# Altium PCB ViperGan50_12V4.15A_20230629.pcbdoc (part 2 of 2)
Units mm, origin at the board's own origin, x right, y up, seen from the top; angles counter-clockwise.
Board outline 450.19 x 402.29 mm, 2 copper layers (Top Layer, Bottom Layer); 71 components, 42 nets, 203 pads, 97 vias.
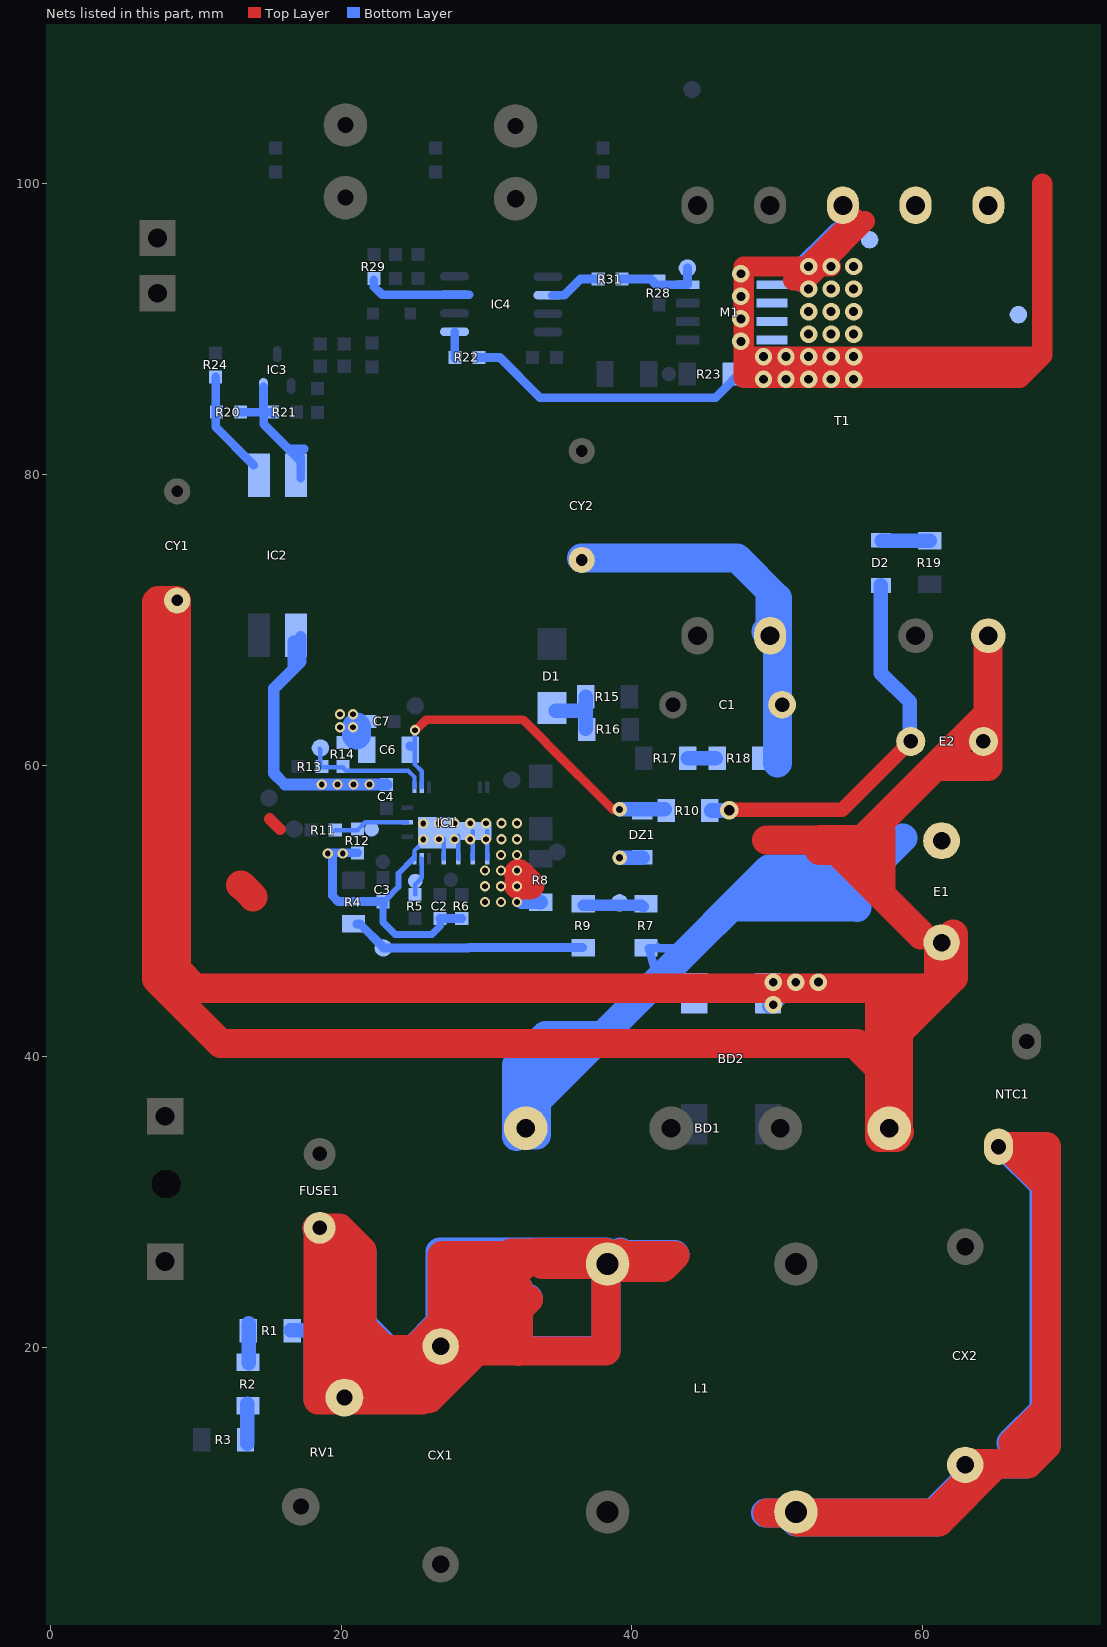
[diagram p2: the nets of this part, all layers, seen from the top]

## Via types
v1: diameter 1.2, hole 0.6, Top Layer to Bottom Layer, 55 vias
v2: diameter 0.7, hole 0.4, Top Layer to Bottom Layer, 38 vias
v3: diameter 1, hole 0.5, Top Layer to Bottom Layer, 3 vias
v4: diameter 1.27, hole 0.711, Top Layer to Bottom Layer, 1 vias

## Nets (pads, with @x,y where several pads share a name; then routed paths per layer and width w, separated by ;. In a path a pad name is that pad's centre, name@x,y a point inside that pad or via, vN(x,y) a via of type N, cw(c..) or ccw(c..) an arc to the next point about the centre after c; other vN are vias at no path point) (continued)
NetCX1_2: CX1.2 FUSE1.1 L1.4 R1.1 RV1.1 | length 356.6
  Top Layer w1: 18.706,21.106 19.296,21.106
  Top Layer w2: FUSE1.1@18.35,28.2 FUSE1.1@18.525,28.2 19.875,28.2 21.425,26.65 21.425,21.775 ; 18.4,20.575 FUSE1.1@18.4,28.075 ; 18.4,20.8 18.4,16.375 25.6,16.375 25.7,16.475 ; 19.175,18.2 20.225,18.2 ; RV1.1@19.7,17.025 RV1.1@20.225,17.025 ; 19.725,22.85 19.725,27.275 ; 20.225,22.625 20.225,18.2 ; 20.225,22.975 21.425,21.775 ; 21.175,19.825 21.425,19.825 ; 21.2,21.6 23.15,19.65 ; 21.425,18.275 21.425,19.825 ; 21.425,21.35 21.425,21.775 ; 25.6,19.825 25.025,19.825 ; 25.675,17.55 25.925,17.8 ; CX1.2@26.95,20.575 26.95,21.75 ; 28.15,22.6 28.15,22.95 ; 32.2,19.7 32.2,19.725 ; 32.2,23.975 32.2,22.6 ; 32.875,23.275 32.2,22.6 ; L1.4@38.475,25.475 42.15,25.475 42.975,26.3 L1.4@39.025,26.3 ; L1.4@39.2,26.475 L1.4@39.025,26.3 ; RV1.1@20.225,17.025 22.225,17.025 ; RV1.1@20.225,17.025 RV1.1@20.225,16.525 20.225,16.475 21.675,16.475 ; RV1.1@20.225,17.025 20.225,18.2 ; 20.225,18.2 23.4,18.2 ; 21.425,19.825 23.375,19.825 25.025,19.825 ; 21.425,19.825 21.425,20.6 ; 21.425,20.6 20.85,20.025 20.3,20.025 21.425,21.15 21.425,20.6 ; 21.675,16.475 22.225,17.025 ; 21.675,16.475 25.375,16.475 ; 22.225,17.025 23.4,18.2 ; 22.225,17.025 25.925,17.025 ; 23.4,18.2 25.025,19.825 ; 23.4,18.2 25.925,18.2 ; 25.025,19.825 26.95,21.75 ; 25.375,16.475 25.925,17.025 ; 25.375,16.475 25.7,16.475 ; 25.7,16.475 26.075,16.475 29.325,19.725 ; 25.925,17.025 25.925,17.8 ; 25.925,17.8 27.85,19.725 29.325,19.725 ; 25.925,17.8 25.925,18.2 ; 25.925,18.2 25.925,19.85 26.15,20.075 26.975,20.075 33.2,26.3 ; 26.95,21.75 28.15,22.95 ; 26.95,21.75 26.95,26.3 28.15,26.3 ; 28.15,22.95 31.5,26.3 ; 28.15,22.95 28.15,26.3 ; 28.15,26.3 31.5,26.3 ; 29.325,19.725 32.2,19.725 ; 29.325,19.725 32.2,22.6 ; 31.5,26.3 33.2,26.3 ; 31.5,26.3 31.675,26.475 33.375,26.475 ; 32.2,19.725 38.225,19.725 L1.4@38.225,25.675 ; 32.2,19.725 32.2,22.6 ; 33.2,26.3 L1.4@38.225,26.3 ; 33.2,26.3 33.825,25.675 L1.4@38.225,25.675 ; 33.2,26.3 33.375,26.475 ; 33.375,26.475 33.4,26.5 38.225,26.5 L1.4@38.225,26.3 ; L1.4@38.225,25.675 38.4,25.675 L1.4@39.025,26.3 ; L1.4@38.225,25.675 L1.4@38.225,26.3 ; L1.4@38.225,26.3 L1.4@39.025,26.3
  Bottom Layer w1: R1.1@16.553,21.156 18.475,21.156 19.296,21.156
  Bottom Layer w2: FUSE1.1@18.35,28.15 FUSE1.1@18.475,28.15 ; 18.4,20.85 18.4,16.425 25.6,16.425 25.7,16.525 ; 18.475,20.625 18.475,21.156 FUSE1.1@18.475,28.15 ; FUSE1.1@18.475,28.2 FUSE1.1@18.475,28.15 ; 19.175,18.25 20.225,18.25 ; RV1.1@19.7,17.075 RV1.1@20.225,17.075 ; 20.225,27.375 20.225,18.25 ; 20.3,20.075 20.85,20.075 ; 21.3,21.7 23.125,19.875 ; 21.325,19.825 21.425,19.825 ; 21.425,18.325 21.425,19.825 ; 25.675,17.6 25.925,17.85 ; CX1.2@25.75,19.825 24.975,19.825 ; CX1.2@27.275,19.75 CX1.2@26.9,20.125 ; 28.375,21.3 28.375,21.525 ; 32.2,19.75 32.2,19.775 ; 32.2,24.025 32.2,22.65 ; 32.875,23.325 32.2,22.65 ; L1.4@38.475,25.525 42.15,25.525 42.975,26.35 L1.4@39.025,26.35 ; L1.4@39.2,26.525 L1.4@39.025,26.35 ; FUSE1.1@18.475,28.15 19.8,28.15 21.425,26.525 21.425,19.825 ; RV1.1@20.225,17.075 22.225,17.075 ; RV1.1@20.225,17.075 RV1.1@20.225,16.525 21.675,16.525 ; RV1.1@20.225,17.075 20.225,18.25 ; 20.225,18.25 23.4,18.25 ; 21.425,19.825 24.975,19.825 ; 21.675,16.525 25.375,16.525 ; 21.675,16.525 22.225,17.075 ; 22.225,17.075 25.925,17.075 ; 22.225,17.075 23.4,18.25 ; 23.4,18.25 24.975,19.825 ; 23.4,18.25 25.925,18.25 ; 24.975,19.825 26.8,21.65 ; 25.375,16.525 25.7,16.525 ; 25.375,16.525 25.925,17.075 ; 25.7,16.525 26.075,16.525 29.325,19.775 ; 25.925,17.075 25.925,17.85 ; 25.925,17.85 27.85,19.775 29.325,19.775 ; 25.925,17.85 25.925,18.25 ; 25.925,18.25 25.925,19.9 26.15,20.125 CX1.2@26.9,20.125 ; 26.8,21.65 28.375,23.225 ; 26.8,21.65 26.8,26.525 28.375,26.525 ; 26.8,21.65 26.8,20.225 CX1.2@26.9,20.125 ; CX1.2@26.9,20.125 26.975,20.125 28.375,21.525 ; 28.375,21.525 33.2,26.35 ; 28.375,21.525 28.375,23.225 ; 28.375,23.225 28.375,26.525 ; 28.375,23.225 31.675,26.525 ; 28.375,26.525 31.675,26.525 ; 29.325,19.775 32.2,22.65 ; 29.325,19.775 32.2,19.775 ; 31.675,26.525 33.375,26.525 ; 32.2,19.775 32.2,22.65 ; 32.2,19.775 38.225,19.775 L1.4@38.225,25.725 ; 33.2,26.35 33.375,26.525 ; 33.2,26.35 33.825,25.725 L1.4@38.225,25.725 ; 33.2,26.35 L1.4@38.225,26.35 ; 33.375,26.525 33.4,26.55 38.225,26.55 L1.4@38.225,26.35 ; L1.4@38.225,25.725 38.4,25.725 L1.4@39.025,26.35 ; L1.4@38.225,25.725 L1.4@38.225,26.35 ; L1.4@38.225,26.35 L1.4@39.025,26.35
NetCX2_1: CX2.1 L1.2 NTC1.2 | length 136.1
  Top Layer w2: 49.325,8.575 L1.2@51.428,8.575 ; L1.2@51.428,8.66 L1.2@51.428,8.575 ; 65.025,11.9 61.1,7.975 51.428,7.975 L1.2@51.428,8.575 ; NTC1.2@65.354,33.778 NTC1.2@65.847,33.778 ; 66.222,13.4 68.497,15.675 ; 68.325,31.3 NTC1.2@65.847,33.778 ; L1.2@51.428,8.575 60.85,8.575 63.075,10.8 63.075,11.9 63.15,11.975 67.25,11.975 68.497,13.222 68.497,15.675 ; NTC1.2@65.847,33.778 68.497,33.778 68.497,15.675
  Bottom Layer w2: 49.175,8.575 L1.2@51.278,8.575 ; L1.2@51.278,8.66 L1.2@51.278,8.575 ; 64.875,11.9 60.95,7.975 51.278,7.975 L1.2@51.278,8.575 ; NTC1.2@65.204,33.778 NTC1.2@65.697,33.778 ; 66.072,13.4 68.347,15.675 ; 68.175,31.3 NTC1.2@65.697,33.778 ; L1.2@51.278,8.575 60.7,8.575 62.925,10.8 CX2.1@62.925,11.9 63,11.975 67.1,11.975 68.347,13.222 68.347,15.675 ; NTC1.2@65.697,33.778 68.347,33.778 68.347,15.675
NetD1_K: D1.K R15.1 R16.1 | length 4.2
  Bottom Layer w1: D1.K@34.775,63.775 36.825,63.775 ; R16.1@36.825,62.525 36.825,63.775 ; R15.1@36.825,64.725 36.825,63.775
NetD2_A: D2.A R19.1 | length 3.3
  Bottom Layer w1: D2.A@57.175,75.45 R19.1@60.475,75.45
NetD2_K: D2.K E2.1 R10.1 | length 26.8
  Top Layer w1: v4@47,56.95 54.475,56.95 E2.1@59.175,61.65
  Bottom Layer w1: R10.1@45.45,56.9 v4@46.45,56.9 ; D2.K@57.125,72.375 57.125,66.35 59.1,64.375 E2.1@59.1,61.5
  other v4: 46.7,56.925
NetIC1_6: IC1.6 pad.11@25.1,52.05 R5.2 | length 2.7
  Bottom Layer w0.3: R5.2@25.095,51.126 25.095,51.82 25.548,52.273 IC1.6@25.548,53.594
NetIC1_9: IC1.9 pad.11@22.1,55.6 R11.2 R12.2 | length 5.2
  Bottom Layer w0.3: R11.2@19.596,55.55 21.121,55.55 21.133,55.562 21.665,56.094 IC1.9@24.548,56.094
NetIC1_11: IC1.11 pad.11@18.575,61.2 R13.1 R14.1 | length 8.6
  Bottom Layer w0.3: pad.11@18.525,61.15 18.575,61.1 18.575,60.025 R13.1@18.681,59.919 ; R13.1@18.745,59.868 20.117,59.868 20.36,59.625 24.625,59.625 25.048,59.202 IC1.11@25.048,58.494
NetIC2_1: IC2.1 R20.1 R24.2 | length 7.2
  Bottom Layer w0.6: R24.2@11.375,86.725 11.375,83.275 IC2.1@14,80.65
NetIC4_2: IC4.2 R31.2 | length 3.6
  Bottom Layer w0.6: IC4.2@34.531,92.341 35.344,92.341 36.449,93.447 R31.2@37.681,93.447
NetIC4_5: IC4.5 R22.2 | length 1.8
  Bottom Layer w0.6: R22.2@27.814,88.011 IC4.5@27.814,89.827
NetIC4_7: IC4.7 R29.2 | length 7.2
  Bottom Layer w0.6: R29.2@22.25,93.409 22.25,92.939 22.822,92.367 IC4.7@27.8,92.367 IC4.7@28.791,92.367
NetM1_D: M1.D pad.26@56.35,96.15 pad.26@66.575,91 R22.1 R23.1 T1.2 T1.3 | length 123.7
  Top Layer w1.4: 47.811,87.7 52.146,87.7 55.245,87.7 67.475,87.7 ; 51.075,93.375 v1@52.014,94.314 ; v1@51.775,93.175 52.914,94.314 ; v1(53.696,94.314) 52.914,94.314 ; T1.3@55.325,97.625 v1@52.014,94.314 ; 56.025,97.425 52.914,94.314 ; 67.575,88.1 47.686,88.1 ; 68.225,100 68.225,88.2 66.686,86.661 47.686,86.661 47.686,88.1 ; 47.686,88.1 47.686,94.314 v1@52.014,94.314 ; v1@52.014,94.314 v1(52.146,94.314) 52.914,94.314
  Bottom Layer w0.6: R22.1@29.476,88.062 30.913,88.062 33.682,85.293 45.745,85.293 47.969,87.517 48.971,87.517
  Bottom Layer w2: 51.525,93.625 54.3,96.4
  other v1: 49.047,86.567 50.597,86.567 52.146,86.567 53.696,86.567 55.245,86.567 49.047,88.117 50.597,88.117 52.146,88.117 53.696,88.117 55.245,88.117 47.498,89.158 52.146,89.666 53.696,89.666 55.245,89.666 47.498,90.708 52.146,91.216 53.696,91.216 55.245,91.216 47.498,92.257 52.146,92.765 53.696,92.765 55.245,92.765 47.498,93.806 55.245,94.314
NetM1_G: M1.G pad.26@43.815,94.209 R28.2 R31.1 | length 5.8
  Bottom Layer w0.6: R31.1@39.319,93.447 41.3,93.447 41.681,93.066 M1.G@43.825,93.066 ; pad.26@43.815,94.209 43.825,94.199 M1.G@43.825,93.066 ; M1.G@43.834,93.066 M1.G@43.825,93.066
NetR1_2: R1.2 R2.1 | length 2.7
  Bottom Layer w1: R2.1@13.644,18.903 R1.2@13.644,21.646
NetR2_2: R2.2 R3.1 | length 2.7
  Bottom Layer w1: R3.1@13.544,13.353 R2.2@13.544,16.096
NetR4_2: pad.11@22.9,47.45 R4.2 R9.1 | length 16.2
  Bottom Layer w0.6: R4.2@21.1,49.1 21.3,49.1 pad.11@22.9,47.5 ; pad.11@22.9,47.45 28.775,47.45 28.8,47.475 R9.1@36.625,47.475
NetR7_1: pad.11@39.15,50.55 R7.1 R9.2 | length 4.2
  Bottom Layer w0.8: R9.2@36.65,50.395 40.655,50.395 R7.1@40.775,50.275
NetR17_2: R17.2 R18.1 | length 1.9
  Bottom Layer w1: R17.2@43.825,60.5 R18.1@45.75,60.5
OUT: IC2.2 IC3.3 R20.2 R21.2 | length 10.9
  Bottom Layer w0.6: R20.2@13.143,84.293 14.669,84.293 ; IC3.3@14.669,86.022 14.669,84.293 ; 14.675,84.35 14.675,84.293 ; R21.2@15.291,84.303 15.301,84.293 14.675,84.293 ; R21.2@15.329,84.226 15.329,84.163 R21.2@15.342,84.15 ; 16.462,81.763 17.463,81.763 ; IC2.2@17.225,79.775 IC2.2@17.225,80.925 ; IC2.2@17.225,81.225 IC2.2@17.225,80.925 ; 14.669,84.293 14.675,84.293 ; 14.675,84.293 14.675,83.475 IC2.2@17.225,80.925
PGND: BD1.4 BD2.4 C2.2 C3.1 C4.2 C6.2 C7.2 CY1.2 DZ1.A E1.2 E2.2 IC1.1 IC1.2 IC1.3 IC1.4 IC1.7 IC1.17 IC2.3 R6.1 R8.2 R12.1 R14.2 T1.10 | length 312.5
  Top Layer w0.8: 15.08,56.32 15.8,55.6
  Top Layer w2: CY1.2@8.6,71.325 7.4,71.325 7.3,71.225 7.3,45.3 11.725,40.875 55.475,40.875 ; CY1.2@8.675,71.35 8.675,45.975 9.975,44.675 60.425,44.675 ; 13.081,51.791 13.125,51.791 13.954,50.962 ; v2@32.207,51.791 32.995,51.791 v2@32.207,52.578 ; 49.25,54.875 55.825,54.875 55.838,54.888 ; 52.912,54.138 54.088,54.138 ; 52.912,54.888 55.838,54.888 ; 53.362,54.864 54.088,54.138 ; 55.525,40.675 56.625,39.575 ; 56.862,54.138 54.088,54.138 ; 57.025,44.4 57.025,42.575 ; 57.088,54.888 55.838,54.888 ; 57.125,51.7 57.125,55.45 ; 57.175,42.425 57.025,42.575 ; BD1.4@57.7,34.574 57.7,44.4 61.1,44.4 ; BD1.4@58.2,34.4 57.025,34.4 57.025,42.575 ; BD1.4@58.4,34.8 58.325,34.875 58.325,41.625 61.1,44.4 ; 59.875,48.35 54.088,54.138 ; E1.2@61.1,47.25 61.1,44.4 ; 61.2,59.925 64.5,59.925 64.5,63.55 ; E1.2@62.1,48.4 62.1,45.4 61.1,44.4 ; T1.10@64.5,68.875 64.5,63.55 ; 55.838,54.888 64.5,63.55
  Bottom Layer w0.3: C3.1@23.063,50.356 C3.1@23.063,50.763 ; IC1.7@24.969,53.594 IC1.7@25.048,53.594 25.048,54.146 25.263,54.361 ; IC1.4@27.048,53.594 IC1.17@27.048,54.916 ; IC1.3@28.048,53.594 IC1.17@28.048,55.169 ; IC1.2@29.048,53.594 IC1.17@29.048,55.483 ; IC1.1@30.048,53.594 IC1.17@30.048,55.499
  Bottom Layer w0.4: C3.1@23.063,50.763 23.95,51.65 23.95,52.575 IC1.7@24.969,53.594
  Bottom Layer w0.5: C3.1@22.875,50.7 C3.1@22.875,50.625 22.875,49.219 23.719,48.375 26.243,48.375 26.822,48.955 26.822,49.45 C2.2@26.797,49.476
  Bottom Layer w0.6: v2(19.075,53.95) 19.114,53.988 R12.1@21.133,53.988 ; 19.406,53.772 19.406,51.029 19.799,50.635 C3.1@22.784,50.635 ; C2.2@26.797,49.476 R6.1@28.296,49.476
  Bottom Layer w0.8: 15.375,65.3 15.375,59.453 16.142,58.686 v2@21.793,58.686 ; 15.4,65.302 16.711,66.614 ; IC2.3@16.711,68.536 16.711,66.614 ; IC2.3@17.225,68.85 17.225,67.127 16.711,66.614 ; v2@21.946,58.686 C4.2@23.114,58.686 C4.2@23.133,58.667
  Bottom Layer w1: v2@32.425,50.625 33.702,50.625 R8.2@33.731,50.595 ; v3(39.15,53.65) DZ1.A@40.75,53.65 ; BD2.4@49.45,43.45 49.628,43.45 v1(49.721,43.542) v1(51.27,45.092) ; BD2.4@49.758,45.092 v1(51.27,45.092) ; v1@52.817,45.092 v1(51.27,45.092)
  Bottom Layer w2: 21.05,62.1 v2@21.05,62.628
  other v1: 49.721,45.092 52.825,45.1
  other v2: 29.896,50.618 30.996,50.618 32.096,50.618 29.896,51.693 30.996,51.693 32.096,51.693 29.896,52.768 30.996,52.768 32.096,52.768 30.996,53.843 32.096,53.843 20.117,53.95 25.654,54.915 26.732,54.921 27.807,54.921 28.882,54.921 29.957,54.921 31.032,54.921 32.107,54.921 25.654,56.007 26.732,56.021 27.807,56.021 28.882,56.021 29.957,56.021 31.032,56.021 32.107,56.021 18.669,58.699 19.761,58.699 20.853,58.699 21.946,58.699 19.927,62.628 20.825,62.625 19.928,63.523 20.828,63.523
VBUS: BD1.1 BD2.1 C1.2 CY2.2 E1.1 R7.2 R18.2 T1.7 | length 112.6
  Bottom Layer w0.6: R7.2@41.55,47.431 R7.2@41.175,47.425 ; 41.781,44.729 41.781,45.231 R7.2@41.175,47.425 ; 41.781,47.472 R7.2@41.175,47.425 ; 43.896,47.431 R7.2@41.175,47.425
  Bottom Layer w2: BD1.1@32.05,34.475 BD1.1@32.05,35.5 ; BD1.1@32.225,34.575 BD1.1@33.425,34.575 ; BD1.1@33.45,34.6 33.45,36.9 ; 35.675,40.925 32.05,37.3 ; CY2.2@36.525,74.275 47.225,74.275 50,71.5 50,60.175 ; 37.925,41.425 34.075,41.425 32.05,39.4 32.05,37.3 ; 46.85,50.25 55.2,50.25 ; 47.875,50.925 55.475,50.925 ; T1.7@49.225,69.204 T1.7@49.508,68.921 49.508,71.717 ; 55.475,50.225 55.475,50.925 ; 55.5,50.925 55.475,50.925 ; 56.325,55.375 56.325,52.75 55.8,52.225 ; 58.625,55 55.85,52.225 55.8,52.225 ; BD1.1@32.05,35.5 32.05,37.3 ; BD1.1@32.05,35.5 33.45,36.9 ; 33.45,36.9 41.781,45.231 49.425,52.875 55.15,52.875 55.8,52.225 ; 55.475,50.925 55.475,51.9 55.8,52.225
VDD: C6.1 DZ1.K IC1.12 R10.2 | length 24.2
  Top Layer w0.6: v2@25.075,62.5 25.2,62.5 25.85,63.15 32.525,63.15 34.15,61.525 34.15,61.5 38.7,56.95 v3@39.15,56.95 ; v3(39.15,56.975) v3@39.175,56.975
  Bottom Layer w0.3: v2(25.075,62.425) 25.075,60.066 25.548,59.593 IC1.12@25.548,58.494
  Bottom Layer w0.6: C6.1@24.741,61.342 C6.1@24.79,61.293
  Bottom Layer w1: v3(39.15,56.975) R10.2@42.25,56.975

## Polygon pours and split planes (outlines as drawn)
PGND on Top Layer "Top Layer-PGND 3" (hatched Horizontal grid 0.3 track 0.3, remove dead copper, pour order 64): -245.008,40.284
12V4A on Top Layer "Top Layer-NetC7_1 2" (hatched Horizontal grid 0.3 track 0.3, remove dead copper, pour order 62): -234.671,70.942
PGND on Top Layer "Top Layer-PGND" (hatched Horizontal grid 0.3 track 0.3, remove dead copper, pour order 60): -185.623,28.473
PGND on Top Layer "Top Layer-PGND 1" (hatched Horizontal grid 0.3 track 0.3, remove dead copper, pour order 59): -185.649,28.956
no net on Top Layer "Top Layer-NetD4_K 1" (hatched Horizontal grid 0.3 track 0.3, remove dead copper, pour order 65): -245.872,81.458
N on Top Layer "Top Layer-NetCX1_1 1" (hatched Horizontal grid 0.3 track 0.3, remove dead copper, pour order 75): -210.033,11.684
no net on Top Layer "Top Layer-No Net" (hatched Horizontal grid 0.3 track 0.3, remove dead copper, pour order 76): -246.481,67.96
12V4A on Top Layer "Top Layer-12V4A" (hatched Horizontal grid 0.2 track 0.2, remove dead copper, pour order 84): 12.02,100.512 13.385,101.801 42.136,101.801 42.633,101.332 42.633,96.481 43.129,96.012 50.255,96.012 50.851,96.574 50.851,107.402 50.429,107.8 32.577,107.8 19.543,107.8 19.543,104.73 19.543,107.8 10.65,107.8
GND2 on Top Layer "Top Layer-GND2" (hatched Horizontal grid 0.2 track 0.2, remove dead copper, pour order 85): 41.478,100.99 41.885,100.584 41.885,96.037 42.621,95.301 44.044,95.301 44.425,94.92 44.425,86.462 44.094,86.131 32.842,86.131 32.36,86.614 32.36,100.99
PGND on Top Layer "Top Layer-PGND 2" (hatched Horizontal grid 0.2 track 0.2, remove dead copper, pour order 118): 7.038,59.461 10.61,55.702 16.304,55.702 17.173,56.617 17.173,63.406 17.619,63.875 21.04,63.875 21.565,63.322 21.565,59.665 22.868,58.293 24.75,58.293 26.536,56.413 30.638,56.413 31.241,55.778 51.246,55.778 57.013,49.708 62.322,49.708 62.925,49.073 62.925,46.939 62.491,46.482 6.821,46.482 5.325,48.057 5.325,59.106 5.663,59.461
NetCX2_1 on Top Layer "Bottom Layer-No Net 2" (solid, pour order 98): 52.13,14.694 47.432,14.694 46.457,13.449 46.457,13.398 47.452,12.128 46.457,10.858 46.457,10.833 47.452,9.563 46.457,8.293 47.452,7.023 52.15,7.023
NetBD1_2 on Top Layer "Bottom Layer-No Net 2" (solid, pour order 99): 52.597,26.715 47.428,26.715 46.355,25.471 46.355,25.42 47.45,24.15 46.355,22.88 46.355,22.855 47.45,21.585 46.355,20.315 47.45,19.045 52.619,19.045
NetCX1_2 on Top Layer "Bottom Layer-No Net 2" (solid, pour order 100): 39.643,18.91 43.961,18.91 44.857,20.155 44.857,20.206 43.942,21.476 44.857,22.746 44.857,22.771 43.942,24.041 44.857,25.311 43.942,26.581 39.625,26.581
N on Top Layer "Bottom Layer-No Net 2" (solid, pour order 101): 39.867,7.125 43.947,7.125 44.794,8.369 44.794,8.42 43.93,9.69 44.794,10.96 44.794,10.985 43.93,12.255 44.794,13.525 43.93,14.795 39.85,14.795
NetM1_D on Bottom Layer "Bottom Layer-NetD40_D" (hatched Horizontal grid 0.2 track 0.2, remove dead copper, pour order 78): 45.836,92.319 51.397,92.319 53.21,93.758 53.21,100.362 53.541,100.625 68.473,100.625 68.783,100.379 68.783,88.004 66.328,86.055 45.701,86.055 45.5,86.215 45.5,92.053
no net on Bottom Layer "Bottom Layer-NetCN3_1 1" (hatched Horizontal grid 0.3 track 0.3, remove dead copper, pour order 69): 12.643,13.56
no net on Bottom Layer "Bottom Layer-N 3" (hatched Horizontal grid 0.3 track 0.3, remove dead copper, pour order 53): 100.686,5.283
no net on Bottom Layer "Bottom Layer-SGND" (hatched Horizontal grid 0.3 track 0.3, remove dead copper, pour order 63): -217.907,62.433
NetC1_1 on Bottom Layer "Bottom Layer-NetC1_2 1" (hatched Horizontal grid 0.3 track 0.3, remove dead copper, pour order 61): -210.744,40.462
no net on Bottom Layer "Bottom Layer-NetCN3_1 2" (hatched Horizontal grid 0.3 track 0.3, remove dead copper, pour order 58): -237.668,2.464
NetCX1_2 on Bottom Layer "Bottom Layer-N 2" (hatched Horizontal grid 0.3 track 0.3, remove dead copper, pour order 56): -210.058,0.686
NetCX1_2 on Bottom Layer "Bottom Layer-N 3" (hatched Horizontal grid 0.3 track 0.3, remove dead copper, pour order 54): -181.635,0.635
no net on Bottom Layer "Bottom Layer-NetCN3_2" (hatched Horizontal grid 0.3 track 0.3, remove dead copper, pour order 68): -231.013,12.979
no net on Bottom Layer "Bottom Layer-NetCN3_1 1" (hatched Horizontal grid 0.3 track 0.3, remove dead copper, pour order 70): -232.893,0.229
no net on Bottom Layer "Bottom Layer-No Net 1" (hatched Horizontal grid 0.2 track 0.2, remove dead copper, pour order 80): 43.834,93.066
no net on Bottom Layer "Bottom Layer-No Net" (hatched Horizontal grid 0.2 track 0.2, remove dead copper, pour order 82): 2.87,99.492
12V4A on Bottom Layer "Bottom Layer-12V4A" (hatched Horizontal grid 0.2 track 0.2, remove dead copper, pour order 83): 11.602,101.321 12.688,102.286 41.935,102.286 42.44,101.778 42.44,96.52 42.945,96.012 50.194,96.012 50.8,96.622 50.8,108.356 50.371,108.788 32.211,108.788 19.179,108.788 10.614,108.788
GND2 on Bottom Layer "Bottom Layer-GND2 2" (hatched Horizontal grid 0.2 track 0.2, remove dead copper, pour order 86): 36.551,88.646 36.805,88.392 44.272,88.392 44.425,88.544 44.425,91.846 44.272,91.999 41.199,91.999 40.869,92.329 36.728,92.329 36.551,92.151
PGND on Bottom Layer "Bottom Layer-PGND 3" (hatched Horizontal grid 0.2 track 0.2, remove dead copper, pour order 87): 21.946,61.265 22.25,61.57 22.25,63.779 22.047,63.983 19.733,63.983 19.5,63.75 19.5,61.525 19.76,61.265
PGND on Bottom Layer "Bottom Layer-PGND 2" (hatched Horizontal grid 0.2 track 0.2, remove dead copper, pour order 88): 25.299,56.439 28.039,56.439 32.228,56.439 32.436,56.249 32.436,49.86 29.151,49.86 29.151,53.753 28.922,53.962 27.146,53.962 26.77,54.305 25.397,54.305 25.298,54.396
PGND on Bottom Layer "Bottom Layer-PGND 1" (hatched Horizontal grid 0.2 track 0.2, remove dead copper, pour order 89): 25.552,55.397
PGND on Bottom Layer "Bottom Layer-PGND" (hatched Horizontal grid 0.2 track 0.2, remove dead copper, pour order 90): 25.552,55.397
12V4A on Bottom Layer "Bottom Layer-12V4A 2" (hatched Horizontal grid 0.2 track 0.2, remove dead copper, pour order 93): 12.497,102.083
NetBD1_3 on Bottom Layer "Bottom Layer-NetCN3_2" (hatched Horizontal grid 0.3 track 0.3, remove dead copper, pour order 67): 14.522,26.311
MOS on Bottom Layer "Bottom Layer-MOS" (hatched Horizontal grid 0.2 track 0.2, remove dead copper, pour order 120): 29.25,59.9 29.25,58.25 29.475,58.025 34.1,58.025 34.55,58.475 34.55,59.95 34.45,60.05 29.4,60.05
NetC5_2 on Bottom Layer "Bottom Layer-NetC14_2" (hatched Horizontal grid 0.2 track 0.2, remove dead copper, pour order 134): 33.025,55.125 34.425,55.125 34.425,53.525 34.375,53.475 33.025,53.475
GND2 on Bottom Layer "Bottom Layer-GND2 1" (hatched Horizontal grid 0.2 track 0.2, remove dead copper, pour order 79): 10.058,97.815 13.233,100.99 41.478,100.99 41.885,100.584 41.884,96.088 41.631,95.834 32.182,95.834 22.309,95.834 17.991,91.516 10.058,91.516
VBUS on Bottom Layer "Bottom Layer-NetBD1_1 3" (hatched Horizontal grid 0.2 track 0.2, remove dead copper, pour order 150): 63.425,57.725
VBUS on Bottom Layer "Bottom Layer-NetBD1_1 4" (hatched Horizontal grid 0.2 track 0.2, remove dead copper, pour order 152): 50.14,70.125 50.506,69.675 50.506,63.125 55.875,56.525 61.59,56.525 63.075,54.7 63.075,53.775 62.77,53.4 58.316,53.4 58.316,54.675 52.58,54.675 48.35,59.875 48.35,69.875 48.37,69.875 48.574,70.125
N on Bottom Layer "Bottom Layer-No Net 2" (solid, pour order 104): 39.942,7.095 43.979,7.095 44.817,8.339 44.817,8.39 43.962,9.66 44.817,10.93 44.817,10.956 43.962,12.226 44.817,13.496 43.962,14.766 39.925,14.766
NetCX2_1 on Bottom Layer "Bottom Layer-No Net 2" (solid, pour order 103): 52.205,14.706 47.489,14.706 46.51,13.462 46.51,13.411 47.509,12.141 46.51,10.871 46.51,10.846 47.509,9.576 46.51,8.306 47.509,7.036 52.225,7.036
NetBD1_2 on Bottom Layer "Bottom Layer-No Net 2" (solid, pour order 102): 52.329,26.556 47.458,26.556 46.447,25.311 46.447,25.26 47.479,23.99 46.447,22.72 46.447,22.695 47.479,21.425 46.447,20.155 47.479,18.885 52.35,18.885
NetCX1_2 on Bottom Layer "Bottom Layer-No Net 2" (solid, pour order 97): 39.867,18.885 43.966,18.885 44.817,20.129 44.817,20.18 43.948,21.45 44.817,22.72 44.817,22.746 43.948,24.016 44.817,25.286 43.948,26.556 39.85,26.556

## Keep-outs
Keep-Out Layer:
  lines w0.2: 1.8,108.1 70.1,108.1 ; 10,46.525 10,65.15

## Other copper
Top Layer:
  rectangle net NetM1_D: 53.924,94.517 68.55,100.675
  rectangle net 12V4A: 11.913,104.517 19.533,107.517
  rectangle net NetM1_D: 47.025,88.05 68.225,94.825
  rectangle net PGND: 10.375,54.85 15.325,64.65
  rectangle net GND2: 22,89.675 31.1,95.125
  rectangle net GND2: 21.375,92.925 31.6,98.85
  rectangle net PGND: 10.3,41.375 56.675,44.8
  rectangle net NetCX2_1: 63.45,12.325 68,14.725
  rectangle net NetCX2_1: 51.7,8.8 62.625,14.675
  rectangle net N: 33.025,9.075 40.925,14.725
  rectangle net NetCX1_2: 32.725,18.775 40.4,25.05
  rectangle net NetBD1_2: 51.275,18.95 63.95,25.175
  pour cut-out: 20.588,94.061 20.588,96.814 21.001,97.227 21.401,96.827 21.401,94.051
  pour cut-out: 21.412,108.885 21.412,106.132 20.999,105.719 20.599,106.119 20.599,108.895
  pour cut-out: 32.412,108.885 32.412,106.132 31.999,105.719 31.599,106.119 31.599,108.895
  pour cut-out: 31.588,94.648 31.588,96.814 32.001,97.227 32.401,96.827 32.401,94.638
Bottom Layer:
  rectangle net NetM1_D: 55.033,92.242 67.25,99.525
  rectangle net NetM1_D: 45.425,91.025 54.875,94.9
  rectangle net VBUS: 50,54.575 53.65,58.925
  rectangle net NetCX1_2: 32.725,18.825 40.4,25.1
  rectangle net NetBD1_2: 51.2,18.925 63.875,25.15
  rectangle net NetCX2_1: 51.55,8.8 62.475,14.675
  rectangle net NetCX2_1: 63.3,12.325 67.85,14.725
  rectangle net N: 33.025,9.125 40.925,14.775
  rectangle net VBUS: 41.05,43.05 45.1,47.9
  pour cut-out: 21.412,108.885 21.412,106.132 20.999,105.719 20.599,106.119 20.599,108.895
  pour cut-out: 20.588,94.061 20.588,96.814 21.001,97.227 21.401,96.827 21.401,94.051
  pour cut-out: 31.588,94.927 31.588,96.814 32.001,97.227 32.401,96.827 32.401,94.917
  pour cut-out: 32.412,108.885 32.412,106.132 31.999,105.719 31.599,106.119 31.599,108.895

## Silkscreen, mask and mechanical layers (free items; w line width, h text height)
Top Overlay:
  circle w0.2: c44.9,17.375 r13
  circle w0.2: c8.721,13.825 r6.854
  circle w0.2: c5.875,104.375 r3.5
  circle w0.2: c65.875,104.3 r3.5
  circle w0.2: c65.8,5.5 r3.5
  rectangle: 9.225,44.35 53.45,45.975
  rectangle: 6.3,46.175 56.25,46.9
  lines w0.2: 4.267,8.359 ccw(c6.175,5.425) 9.329,6.942
  lines w0.254: 37.2,21.7 38.975,21.7 ; 37.275,12.675 39.05,12.675 ; 50.65,12.675 52.425,12.675 ; 50.675,21.725 52.45,21.725
  text "+12V / GND" at 13.55,108.35 h1.2 r270
  text "N" at 12.7,25.45 h1.2
Bottom Overlay:
  lines w0.2: 3.875,3.176 67.925,3.176 ; 3.907,3.25 3.907,107.575 ; 67.982,3.325 67.982,107.65
Bottom Paste:
  region: 45.376,26.276 42.378,26.276 42.378,7.087 45.376,7.087
  region: 49.164,26.225 46.167,26.225 46.167,7.036 49.164,7.036
Mechanical 1:
  circle w0.254: c6.2,5.45 r2
  circle w0.254: c65.85,5.6 r2
  circle w0.254: c5.925,104.375 r2
  circle w0.254: c65.925,104.3 r2
  lines w0.2: 70.003,0.126 70.003,108.1 ; 1.55,0.5 1.55,108.175 69.925,108.175 69.925,0.5 1.55,0.5
  lines w1: 28.55,61.375 28.55,57.861 29.134,57.277 35.85,57.277
  lines w1.5: 5.575,75.125 11.8,75.075 ; 12.325,75.1 18.55,75.05 ; 32.3,66.475 44.55,66.475 ; 33.25,77.75 39.475,77.7 ; 44.85,66.4 47.015,68.565 47.015,70.235 45.175,72.075 ; 46.825,36.85 46.825,33.8 48.95,31.675 ; 49.25,31.75 63.125,31.75 65.65,29.225 ; 60.15,51.8 63.8,51.7

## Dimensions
1.55,0.5 to 69.925,0.5 on Mechanical 1
1.55,108.175 to 69.925,0.5 on Mechanical 1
